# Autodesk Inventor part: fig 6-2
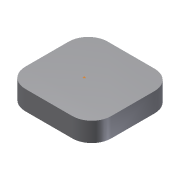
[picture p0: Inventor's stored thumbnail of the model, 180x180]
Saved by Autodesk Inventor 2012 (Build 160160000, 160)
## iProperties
Created: 2004-05
Part Number: fig 6-2
Document SubType Name: Modeling
Designer: CADCIM Technologies
Manufacturer: Standard
Standards Organization: Custom
Density: 1 g/cm^3
Material: Default
Author: CADCIM Technologies
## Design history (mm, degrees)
sketch "Sketch1"
  geometry: L1 (0, 0)-(44.293, 0); L2 (44.293, 0)-(44.293, 42.442); L3 (44.293, 42.442)-(0, 42.442); L4 (0, 42.442)-(0, 0)
  constraints: 8 end point, 2 parallel, 1 horizontal, 1 perpendicular
extrude "Extrusion1" new body sketch "Sketch1" distance "d0" = 10; taper "d1" = 0 deg
fillet "Fillet1" dims "d2" = 10
sketch "Sketch2"
  geometry: 1 further point
sketch "Sketch3"
  geometry: L1 (10, 42.442)-(34.293, 42.442) reference; L2 (0, 10)-(0, 32.442) reference; L3 (34.293, 0)-(10, 0) reference; L4 (44.293, 32.442)-(44.293, 10) reference; A1 r 10 centre (34.293, 32.442) between (44.293, 32.442) and (34.293, 42.442) reference; A2 r 10 centre (10, 32.442) between (10, 42.442) and (0, 32.442) reference; A3 r 10 centre (10, 10) between (0, 10) and (10, 0) reference; A4 r 10 centre (34.293, 10) between (34.293, 0) and (44.293, 10) reference; 1 further point
workpoint "Work Point1"
body "Solid1"
